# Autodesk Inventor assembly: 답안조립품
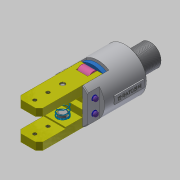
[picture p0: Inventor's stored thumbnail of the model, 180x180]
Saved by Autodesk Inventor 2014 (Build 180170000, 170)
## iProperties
Created: 2019-02
Part Number: 답안조립품
Document SubType Name: Assembly
Designer: 602-10
Author: 602-10
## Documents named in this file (11)
- C:\Users\602-10\Desktop\490208V1006\답안조립품.iam
- C:\Users\602-10\Desktop\490208V1006\본체.ipt
- C:\Users\602-10\Desktop\490208V1006\O-링.ipt
- C:\Users\602-10\Desktop\490208V1006\피스톤.ipt
- C:\Users\602-10\Desktop\490208V1006\핑거.ipt
- C:\Users\602-10\Desktop\490208V1006\평행핀 6x28.ipt
- C:\Users\602-10\Desktop\490208V1006\부시.ipt
- C:\Users\602-10\Desktop\490208V1006\핀.ipt
- C:\Users\602-10\Desktop\490208V1006\E-링.ipt
- C:\Users\602-10\Desktop\490208V1006\가이드핀.ipt
- C:\Users\602-10\Desktop\490208V1006\스프링.ipt
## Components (13 placed, 6 different names)
1. O-링:1
2. O-링:2
3. 피스톤:1
4. 핑거:1
5. 핑거:2
6. 핀:1
7. 핀:2
8. E-링:1
9. E-링:2
10. E-링:3
11. E-링:4
12. 가이드핀:1
13. 가이드핀:2
